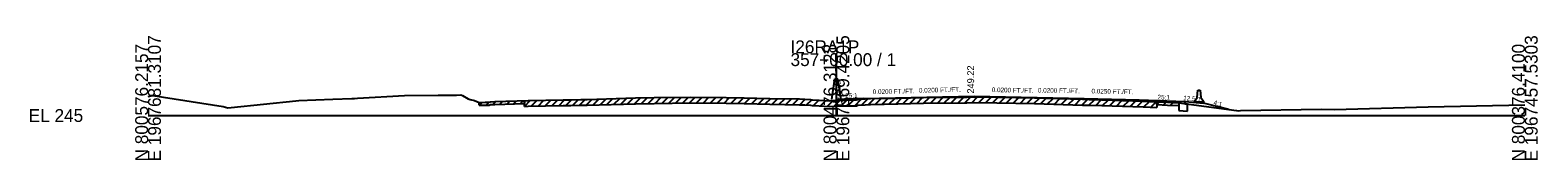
# Model space of a CAD drawing. Extents: x -26 to 304, y -10 to 7527.
# Drawn here: x -25.7 to 302.8, y 3490.3 to 3517.3 of the extents above; entities that cross this region are included whole.
import ezdxf

# ---------------------------------------------------------------- set-up
doc = ezdxf.new("R2010")
doc.units = 0
for name, color, linetype in [('Default', 7, 'Continuous'), ('RD_GPK_XS_Cell', 7, 'Continuous'), ('RD_XS_Base', 7, 'Continuous'), ('RD_XS_Box', 7, 'Continuous'), ('RD_XS_EarthShd', 7, 'Continuous'), ('RD_XS_ExGround', 7, 'Continuous'), ('RD_XS_ExPaveRet', 7, 'Continuous'), ('RD_XS_Misc_Line', 7, 'Continuous'), ('RD_XS_Pave', 7, 'Continuous'), ('RD_XS_PaveShd', 7, 'Continuous'), ('RD_XS_TX_Elev_EX', 7, 'Continuous'), ('RD_XS_TX_Elev_PR', 7, 'Continuous'), ('RD_XS_TX_Misc', 7, 'Continuous'), ('RD_XS_TX_MkPT', 7, 'Continuous'), ('RD_XS_TX_Profile', 7, 'Continuous'), ('RD_XS_TX_Station', 7, 'Continuous')]:
    doc.layers.add(name, color=color, linetype=linetype)

msp = doc.modelspace()

# ---------------------------------------------------------------- linework, layer by layer
at = {"layer": 'Default'}
for p, q in [((228.58, 3503.96), (228.75, 3505.55)), ((228.75, 3505.55), (229.25, 3505.55)), ((229.25, 3505.55), (229.42, 3503.96)), ((228, 3503.13), (228.58, 3503.96)), ((228, 3502.88), (228, 3503.13)), ((230, 3502.88), (228, 3502.88)), ((229.42, 3503.96), (230, 3503.13)), ((230, 3503.13), (230, 3502.88))]:
    msp.add_line(p, q, dxfattribs=at)
at = {"layer": 'RD_GPK_XS_Cell'}
for p, q in [((150, 3500), (150, 3513.57)), ((0, 3500), (150, 3500)), ((150, 3500), (300, 3500))]:
    msp.add_line(p, q, dxfattribs=at)
at = {"layer": 'RD_XS_Base'}
for p, q in [((150, 3503.3), (150, 3503.5)), ((226, 3502.48), (226, 3503.04)), ((226.5, 3502.46), (226, 3502.48)), ((226.5, 3500.98), (226.5, 3502.46)), ((224.62, 3501.06), (226.5, 3500.98))]:
    msp.add_line(p, q, dxfattribs=at)
at = {"layer": 'RD_XS_Box'}
msp.add_line((235.55, 3501.33), (230, 3502.72), dxfattribs=at)
at = {"layer": 'RD_XS_EarthShd'}
for p, q in [((149, 3503.52), (149.67, 3508)), ((150, 3508), (149.67, 3508)), ((150, 3508), (150.33, 3508)), ((151, 3503.52), (150.33, 3508)), ((226, 3503.04), (230, 3502.72))]:
    msp.add_line(p, q, dxfattribs=at)
at = {"layer": 'RD_XS_ExGround'}
msp.add_lwpolyline([(0, 3504.18), (1.01, 3504.39), (16.33, 3501.93), (17.41, 3501.69), (18.14, 3501.76), (32.23, 3503.21), (32.83, 3503.27), (40.26, 3503.55), (44.41, 3503.72), (44.96, 3503.74), (45.64, 3503.78), (55.85, 3504.37), (63.19, 3504.42), (65.51, 3504.46), (67.24, 3504.47), (68.12, 3504.52), (68.53, 3504.33), (69.74, 3503.66), (70.17, 3503.51), (71.13, 3503.25), (72.16, 3502.85), (73.47, 3502.88), (74.34, 3502.91), (74.6, 3503.01), (75.57, 3503.04), (82.83, 3503.27), (90.45, 3503.41), (92.11, 3503.44), (94.31, 3503.48), (95.68, 3503.52), (106.22, 3503.83), (110.31, 3503.9), (118.2, 3504.03), (125.99, 3503.91), (129.9, 3503.85), (135.48, 3503.74), (141.92, 3503.61), (143.13, 3503.56), (144.37, 3503.51), (144.7, 3503.43), (146.22, 3503.36), (148.39, 3503.23), (150.12, 3503.31), (151.02, 3503.34), (152.13, 3503.36), (154.37, 3503.39), (154.63, 3503.51), (156.23, 3503.6), (157.45, 3503.68), (163.4, 3503.81), (168.97, 3503.93), (178.39, 3504.03), (181.11, 3504.06), (184.94, 3503.98), (193.14, 3503.84), (203.64, 3503.53), (205.09, 3503.49), (207.84, 3503.41), (216.83, 3503.14), (222.14, 3502.89), (224.62, 3502.78), (237.15, 3501.12), (237.54, 3501.05), (238.08, 3501.06), (255.7, 3501.38), (258.55, 3501.29), (278.92, 3501.86), (300, 3502.3)], dxfattribs=at)
at = {"layer": 'RD_XS_ExPaveRet'}
for p, q in [((72.16, 3502.23), (72.16, 3502.85)), ((72.16, 3502.23), (73.47, 3502.25)), ((73.47, 3502.25), (74.34, 3502.28)), ((74.34, 3502.28), (74.6, 3502.38)), ((74.6, 3502.38), (75.57, 3502.42)), ((75.57, 3502.42), (82, 3502.62)), ((82, 3502), (82, 3503.25)), ((82, 3503.25), (82, 3502.62)), ((82.83, 3502.02), (90.45, 3502.16)), ((90.45, 3502.16), (92.11, 3502.19)), ((92.11, 3502.19), (94.31, 3502.23)), ((94.31, 3502.23), (95.68, 3502.27)), ((95.68, 3502.27), (106.22, 3502.58)), ((106.22, 3502.58), (110.31, 3502.65)), ((110.31, 3502.65), (118.2, 3502.78)), ((118.2, 3502.78), (125.99, 3502.66)), ((125.99, 3502.66), (129.9, 3502.6)), ((129.9, 3502.6), (135.48, 3502.49)), ((135.48, 3502.49), (141.92, 3502.36)), ((141.92, 3502.36), (143.13, 3502.31)), ((143.13, 3502.31), (144.37, 3502.26)), ((144.37, 3502.26), (144.7, 3502.18)), ((144.7, 3502.18), (146.22, 3502.11)), ((154.37, 3502.14), (154.63, 3502.26)), ((154.63, 3502.26), (156.23, 3502.35)), ((156.23, 3502.35), (157.45, 3502.43)), ((157.45, 3502.43), (163.4, 3502.56)), ((163.4, 3502.56), (168.97, 3502.68)), ((168.97, 3502.68), (178.39, 3502.78)), ((178.39, 3502.78), (181.11, 3502.81)), ((181.11, 3502.81), (184.94, 3502.73)), ((184.94, 3502.73), (193.14, 3502.59)), ((193.14, 3502.59), (203.64, 3502.28)), ((203.64, 3502.28), (205.09, 3502.24)), ((205.09, 3502.24), (207.84, 3502.16)), ((219.78, 3503), (219.78, 3501.75)), ((219.78, 3502.38), (219.78, 3503)), ((219.78, 3502.38), (222.14, 3502.27)), ((222.14, 3502.27), (224.62, 3502.16)), ((224.62, 3502.78), (224.62, 3502.16)), ((82, 3502), (82.83, 3502.02)), ((146.22, 3502.11), (148.39, 3501.98)), ((148.39, 3501.98), (150.12, 3502.06)), ((150.12, 3502.06), (151.02, 3502.09)), ((151.02, 3502.09), (152.13, 3502.11)), ((152.13, 3502.11), (154.37, 3502.14)), ((207.84, 3502.16), (216.83, 3501.89)), ((216.83, 3501.89), (219.78, 3501.75))]:
    msp.add_line(p, q, dxfattribs=at)
at = {"layer": 'RD_XS_Misc_Line'}
for p, q in [((72.16, 3502.23), (72.79, 3502.87)), ((73.66, 3502.26), (74.3, 3502.91)), ((75.16, 3502.4), (75.8, 3503.05)), ((76.66, 3502.45), (77.3, 3503.1)), ((78.16, 3502.5), (78.8, 3503.14)), ((79.66, 3502.55), (80.3, 3503.19)), ((81.16, 3502.6), (81.8, 3503.24)), ((82, 3502), (83.28, 3503.28)), ((83.5, 3502.04), (84.77, 3503.31)), ((85, 3502.06), (86.27, 3503.34)), ((86.5, 3502.09), (87.77, 3503.36)), ((88, 3502.12), (89.27, 3503.39)), ((89.5, 3502.14), (90.77, 3503.42)), ((91, 3502.17), (92.27, 3503.44)), ((92.5, 3502.2), (93.77, 3503.47)), ((94, 3502.22), (95.28, 3503.5)), ((95.5, 3502.26), (96.79, 3503.55)), ((97, 3502.31), (98.29, 3503.6)), ((98.5, 3502.35), (99.79, 3503.64)), ((100, 3502.4), (101.29, 3503.69)), ((101.5, 3502.44), (102.79, 3503.73)), ((103, 3502.49), (104.29, 3503.78)), ((104.5, 3502.53), (105.79, 3503.82)), ((106, 3502.58), (107.27, 3503.85)), ((107.5, 3502.6), (108.77, 3503.88)), ((109, 3502.63), (110.27, 3503.9)), ((110.5, 3502.65), (111.77, 3503.92)), ((112, 3502.68), (113.27, 3503.95)), ((113.5, 3502.7), (114.77, 3503.97)), ((115, 3502.73), (116.27, 3504)), ((116.5, 3502.75), (117.77, 3504.02)), ((118, 3502.78), (119.24, 3504.02)), ((119.5, 3502.76), (120.73, 3503.99)), ((121, 3502.74), (122.23, 3503.97)), ((122.5, 3502.72), (123.73, 3503.95)), ((124, 3502.69), (125.23, 3503.92)), ((125.5, 3502.67), (126.73, 3503.9)), ((127, 3502.65), (128.23, 3503.88)), ((128.5, 3502.63), (129.73, 3503.86)), ((130, 3502.6), (131.22, 3503.83)), ((131.5, 3502.57), (132.72, 3503.79)), ((133, 3502.54), (134.22, 3503.76)), ((134.5, 3502.51), (135.72, 3503.73)), ((136, 3502.48), (137.23, 3503.7)), ((137.5, 3502.45), (138.73, 3503.67)), ((139, 3502.42), (140.23, 3503.64)), ((140.5, 3502.38), (141.73, 3503.61)), ((142, 3502.35), (143.21, 3503.56)), ((143.5, 3502.3), (144.65, 3503.44)), ((145, 3502.16), (146.2, 3503.36)), ((146.5, 3502.09), (147.68, 3503.27)), ((148, 3502), (149.27, 3503.27)), ((149.5, 3502.03), (150.81, 3503.34)), ((151, 3502.09), (152.27, 3503.37)), ((152.5, 3502.12), (153.77, 3503.39)), ((154, 3502.14), (155.42, 3503.56)), ((155.5, 3502.31), (156.83, 3503.64)), ((157, 3502.4), (158.3, 3503.7)), ((158.5, 3502.45), (159.78, 3503.73)), ((160, 3502.49), (161.28, 3503.76)), ((161.5, 3502.52), (162.78, 3503.79)), ((163, 3502.55), (164.28, 3503.83)), ((164.5, 3502.58), (165.78, 3503.86)), ((166, 3502.62), (167.28, 3503.9)), ((167.5, 3502.65), (168.78, 3503.93)), ((169, 3502.68), (170.26, 3503.95)), ((170.5, 3502.7), (171.76, 3503.96)), ((172, 3502.72), (173.26, 3503.98)), ((173.5, 3502.73), (174.76, 3503.99)), ((175, 3502.75), (176.26, 3504.01)), ((176.5, 3502.76), (177.76, 3504.03)), ((178, 3502.78), (179.26, 3504.04)), ((179.5, 3502.79), (180.76, 3504.06)), ((181, 3502.81), (182.23, 3504.04)), ((182.5, 3502.78), (183.72, 3504.01)), ((184, 3502.75), (185.23, 3503.98)), ((185.5, 3502.73), (186.73, 3503.95)), ((187, 3502.7), (188.23, 3503.93)), ((188.5, 3502.67), (189.73, 3503.9)), ((190, 3502.65), (191.23, 3503.87)), ((191.5, 3502.62), (192.73, 3503.85)), ((193, 3502.59), (194.22, 3503.81)), ((194.5, 3502.55), (195.71, 3503.76)), ((196, 3502.51), (197.21, 3503.72)), ((197.5, 3502.46), (198.71, 3503.68)), ((199, 3502.42), (200.21, 3503.63)), ((200.5, 3502.37), (201.71, 3503.59)), ((202, 3502.33), (203.21, 3503.54)), ((203.5, 3502.28), (204.71, 3503.5)), ((205, 3502.24), (206.21, 3503.45)), ((206.5, 3502.2), (207.71, 3503.41)), ((208, 3502.15), (209.21, 3503.37)), ((209.5, 3502.11), (210.71, 3503.32)), ((211, 3502.06), (212.21, 3503.28)), ((212.5, 3502.02), (213.71, 3503.23)), ((214, 3501.97), (215.21, 3503.19)), ((215.5, 3501.93), (216.71, 3503.14)), ((217, 3501.88), (218.19, 3503.08)), ((218.5, 3501.81), (219.69, 3503.01)), ((219.78, 3502.38), (220.38, 3502.98)), ((221.28, 3502.31), (221.88, 3502.91)), ((222.78, 3502.24), (223.38, 3502.84))]:
    msp.add_line(p, q, dxfattribs=at)
at = {"layer": 'RD_XS_Pave'}
for p, q in [((156, 3503.74), (180, 3504.22)), ((180, 3504.22), (204, 3503.74)), ((204, 3503.74), (216, 3503.44))]:
    msp.add_line(p, q, dxfattribs=at)
at = {"layer": 'RD_XS_PaveShd'}
for p, q in [((156, 3503.74), (150, 3503.5)), ((216, 3503.44), (226, 3503.04))]:
    msp.add_line(p, q, dxfattribs=at)
at = {"layer": 'RD_XS_TX_Elev_PR'}
for p, q in [((150, 3503.3), (150.12, 3503.31)), ((150.12, 3503.31), (151.02, 3503.34)), ((151.02, 3503.34), (152.13, 3503.36)), ((152.13, 3503.36), (154.37, 3503.39)), ((154.37, 3503.39), (154.63, 3503.51)), ((154.63, 3503.51), (156.23, 3503.6)), ((156.23, 3503.6), (157.45, 3503.68)), ((157.45, 3503.68), (163.4, 3503.81)), ((163.4, 3503.81), (168.97, 3503.93)), ((168.97, 3503.93), (178.39, 3504.03)), ((178.39, 3504.03), (181.11, 3504.06)), ((181.11, 3504.06), (184.94, 3503.98)), ((184.94, 3503.98), (193.14, 3503.84)), ((193.14, 3503.84), (203.64, 3503.53)), ((203.64, 3503.53), (205.09, 3503.49)), ((205.09, 3503.49), (207.84, 3503.41)), ((207.84, 3503.41), (216.83, 3503.14)), ((216.83, 3503.14), (219.78, 3503)), ((219.78, 3503), (222.14, 3502.89)), ((222.14, 3502.89), (224.62, 3502.78)), ((224.62, 3502.78), (224.62, 3501.06))]:
    msp.add_line(p, q, dxfattribs=at)

# ---------------------------------------------------------------- texts
at = {"layer": 'RD_GPK_XS_Cell'}
for s, p in [('N 800576.2157', (0, 3490)), ('E 1967681.3107', (2.8, 3490)), ('N 800476.3128', (150, 3490)), ('E 1967569.4205', (152.8, 3490)), ('N 800376.4100', (300, 3490)), ('E 1967457.5303', (302.8, 3490))]:
    msp.add_text(s, height=2.8, rotation=90, dxfattribs=at).set_placement(p)
for s, p in [('I26RA1P', (140, 3513.57)), ('357+00.00 / 1', (140, 3510.77)), ('EL 245', (-26, 3498.6))]:
    msp.add_text(s, height=2.8, dxfattribs=at).set_placement(p)
at = {"layer": 'RD_XS_TX_Elev_EX'}
msp.add_text('248.30', height=1, rotation=90, dxfattribs=at).set_placement((151, 3503.3))
at = {"layer": 'RD_XS_TX_Misc'}
msp.add_text('12.5:1', height=1, rotation=355.4261, dxfattribs=at).set_placement((225.54, 3503.33))
at = {"layer": 'RD_XS_TX_MkPT'}
for rotation, p in [(2.2906, (151.94, 3503.83)), (357.7094, (219.96, 3503.53))]:
    msp.add_text('25:1', height=1, rotation=rotation, dxfattribs=at).set_placement(p)
at = {"layer": 'RD_XS_TX_Profile'}
for s, rotation, p in [('0.0200 FT./FT.', 1.1458, (157.92, 3504.67)), ('0.0200 FT./FT.', 1.1458, (167.98, 3504.98)), ('0.0200 FT./FT.', 358.5679, (183.83, 3505.13)), ('0.0200 FT./FT.', 358.8542, (193.89, 3505.02)), ('0.0250 FT./FT.', 358.8542, (205.57, 3504.83)), ('4:1', 345.9638, (232.08, 3502.38))]:
    msp.add_text(s, height=1, rotation=rotation, dxfattribs=at).set_placement(p)
at = {"layer": 'RD_XS_TX_Station'}
msp.add_text(' 249.22', height=1.5, rotation=90, dxfattribs=at).set_placement((180, 3504.22))

doc.saveas('drawing.dxf')
